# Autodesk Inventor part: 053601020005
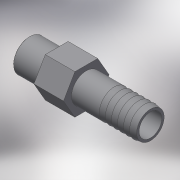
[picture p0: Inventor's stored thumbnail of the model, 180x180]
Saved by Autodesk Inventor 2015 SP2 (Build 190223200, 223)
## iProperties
Created: 2017-10
Part Number: 053601020005
Material: Generic
Description: PLASSON THREADED HOSE NOZZLE 1/2"-20
Document SubType Name: Modeling
Designer: KIM
Density: 1 g/cm^3
Appearance: Default
Author: KIM
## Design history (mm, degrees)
derived "053601.ipt"
feature "Solid1::053601.ipt"
tag "TaggingFeature1"
body "Solid1"
other parameters: "d0" = 64, "d1" = 170 deg, "d6" = 14.6685, "d8" = 19.2, "d9" = 20.955, "d10" = 26, "d11" = 16, "d12" = 12, "d13" = 12, "d14" = 0, "d15" = 0.12, "d_" = 12, "H_" = 64, "R_" = 20.955, "C_" = 26, "B_" = 12, "Lt_" = 16
